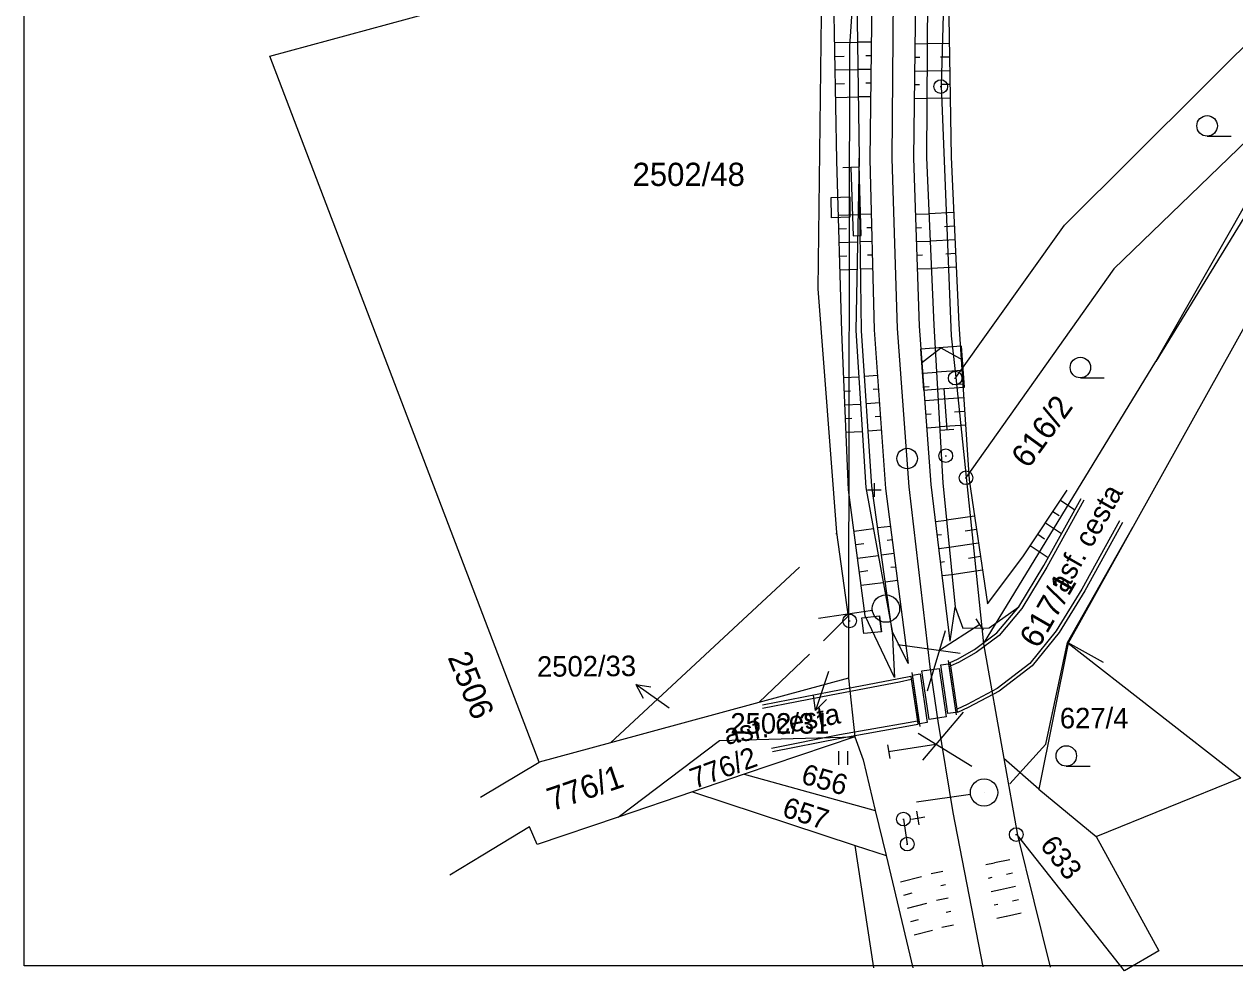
# Model space of a CAD drawing. Extents: x -558358 to -557517, y -1073786 to -1073189.
# Drawn here: x -558357.5 to -558268.9, y -1073784.4 to -1073715.2 of the extents above; entities that cross this region are included whole.
import ezdxf

# ---------------------------------------------------------------- set-up
doc = ezdxf.new("R2010")
doc.units = 0
for name, color, linetype in [('Body', 7, 'Continuous'), ('bubliny', 7, 'Continuous'), ('Hranice parcel', 7, 'Continuous'), ('Kolej', 7, 'Continuous'), ('Lomové body_krizky', 7, 'Continuous'), ('Návěst místo trati', 7, 'Continuous'), ('Návěst ostatní', 7, 'Continuous'), ('Parcelní čísla', 7, 'Continuous'), ('Plot - zábradlí', 7, 'Continuous'), ('Pop  PČ popisy', 7, 'Continuous'), ('Přejezd - štěrkové lože', 7, 'Continuous'), ('Sonda - šrafa - vrstevnice', 7, 'Continuous'), ('Svazek obcí údolí Desné', 7, 'Continuous'), ('Vedení nerozlišené', 7, 'Continuous'), ('Vrstva 1', 7, 'Continuous'), ('Značky kultur', 7, 'Continuous'), ('ŽKN drážní hranice', 7, 'Continuous')]:
    doc.layers.add(name, color=color, linetype=linetype)

msp = doc.modelspace()

# ---------------------------------------------------------------- linework, layer by layer
at = {"layer": 'Body'}
for p, q in [((-558298.48, -1073727.885), (-558297.122, -1073727.85)), ((-558297.117, -1073729.344), (-558298.447, -1073729.379)), ((-558296.242, -1073758.631), (-558294.944, -1073758.48)), ((-558294.789, -1073759.67), (-558296.101, -1073759.777))]:
    msp.add_line(p, q, dxfattribs=at)
for points in [[(-558297.122, -1073727.85), (-558297.117, -1073729.344), (-558298.447, -1073729.379), (-558298.48, -1073727.885), (-558297.122, -1073727.85)], [(-558298.447, -1073729.379), (-558298.447, -1073729.379), (-558298.48, -1073727.885), (-558298.48, -1073727.885)], [(-558297.117, -1073729.344), (-558297.117, -1073729.344), (-558297.122, -1073727.85), (-558297.122, -1073727.85)], [(-558294.944, -1073758.48), (-558294.789, -1073759.67), (-558296.101, -1073759.777), (-558296.242, -1073758.631), (-558294.944, -1073758.48)], [(-558294.789, -1073759.67), (-558294.789, -1073759.67), (-558294.944, -1073758.48), (-558294.944, -1073758.48)]]:
    msp.add_lwpolyline(points, dxfattribs=at)
at = {"layer": 'bubliny'}
for p, q in [((-558293.243, -1073773.359), (-558293.143, -1073773.359)), ((-558293.193, -1073773.359), (-558292.916, -1073775.189)), ((-558292.966, -1073775.189), (-558292.866, -1073775.189))]:
    msp.add_line(p, q, dxfattribs=at)
for points in [[(-558277.161, -1073751.663), (-558279.929, -1073756.667), (-558281.804, -1073759.714), (-558283.763, -1073762.159), (-558286.192, -1073764.005), (-558288.469, -1073765.207), (-558289.239, -1073765.561), (-558289.273, -1073765.325), (-558289.731, -1073762.148), (-558289.772, -1073761.903), (-558289.238, -1073761.663), (-558288.001, -1073760.952), (-558286.366, -1073759.742), (-558284.741, -1073757.826), (-558282.921, -1073754.818), (-558280.188, -1073749.911)], [(-558279.986, -1073750.021), (-558282.709, -1073754.924), (-558284.536, -1073757.951), (-558286.196, -1073759.921), (-558287.876, -1073761.169), (-558289.171, -1073761.901), (-558289.731, -1073762.148)], [(-558277.378, -1073751.548), (-558280.147, -1073756.544), (-558282.018, -1073759.595), (-558283.934, -1073761.983), (-558286.347, -1073763.816), (-558288.522, -1073764.981), (-558289.273, -1073765.325)], [(-558303.504, -1073765.012), (-558298.501, -1073764.02), (-558293.523, -1073763.084), (-558292.659, -1073762.9), (-558292.626, -1073763.133), (-558292.174, -1073766.197), (-558292.136, -1073766.428), (-558292.793, -1073766.551), (-558297.819, -1073767.452), (-558302.784, -1073768.441)], [(-558303.496, -1073765.249), (-558298.474, -1073764.266), (-558293.477, -1073763.32), (-558292.626, -1073763.133)], [(-558292.174, -1073766.197), (-558292.85, -1073766.309), (-558297.868, -1073767.199), (-558302.848, -1073768.199)]]:
    msp.add_lwpolyline(points, dxfattribs=at)
for centre in [(-558293.193, -1073773.359), (-558292.916, -1073775.189)]:
    msp.add_circle(centre, 0.5, dxfattribs=at)
at = {"layer": 'Hranice parcel'}
for p, q in [((-558339.57, -1073717.56), (-558299.09, -1073706.57)), ((-558319.85, -1073769.2), (-558339.57, -1073717.56)), ((-558274.72, -1073739.9), (-558262.39, -1073718.25)), ((-558259.48, -1073721.62), (-558281.15, -1073760.49)), ((-558287.34, -1073760.54), (-558274.72, -1073739.9)), ((-558300.796, -1073754.924), (-558314.63, -1073767.78)), ((-558281.15, -1073760.49), (-558283.28, -1073771.17)), ((-558281.15, -1073760.49), (-558268.5, -1073770.34)), ((-558300.06, -1073761.284), (-558303.78, -1073764.84)), ((-558297.22, -1073763.06), (-558303.78, -1073764.84)), ((-558303.78, -1073764.84), (-558314.63, -1073767.78)), ((-558296.74, -1073767.33), (-558304.84, -1073770.08)), ((-558314.63, -1073767.78), (-558319.85, -1073769.2)), ((-558283.28, -1073771.17), (-558285.85, -1073768.92)), ((-558324.15, -1073771.75), (-558319.85, -1073769.2)), ((-558304.84, -1073770.08), (-558308.63, -1073771.36)), ((-558304.84, -1073770.08), (-558295.26, -1073772.72)), ((-558279.1, -1073774.62), (-558268.5, -1073770.34)), ((-558308.63, -1073771.36), (-558314.07, -1073773.21)), ((-558308.63, -1073771.36), (-558296.72, -1073775.29)), ((-558283.28, -1073771.17), (-558279.1, -1073774.62)), ((-558314.07, -1073773.21), (-558319.99, -1073775.22)), ((-558323.98, -1073776), (-558326.38, -1073777.46))]:
    msp.add_line(p, q, dxfattribs=at)
for points in [[(-558289.37, -1073741.07), (-558281.4, -1073729.91), (-558261.12, -1073709.7)], [(-558260.45, -1073716.38), (-558262.32, -1073719.63), (-558274.72, -1073739.9)], [(-558262.39, -1073718.25), (-558277.79, -1073733.11), (-558288.61, -1073748.35)], [(-558314.07, -1073773.21), (-558306.66, -1073767.6), (-558296.74, -1073767.33)], [(-558319.99, -1073775.22), (-558320.55, -1073773.92), (-558323.98, -1073776)], [(-558279.1, -1073774.62), (-558274.51, -1073783), (-558277.02, -1073784.45), (-558284.85, -1073774.53)]]:
    msp.add_lwpolyline(points, dxfattribs=at)
at = {"layer": 'Kolej'}
msp.add_lwpolyline([(-558287.365, -1073784.156), (-558289.56, -1073772.871), (-558290.655, -1073766.206), (-558291.244, -1073762.209), (-558292.77, -1073749.061), (-558293.618, -1073737.469), (-558294.023, -1073725.055), (-558293.93, -1073713.176), (-558293.343, -1073701.022), (-558292.273, -1073689.007), (-558290.767, -1073677.306), (-558288.802, -1073665.65), (-558286.315, -1073653.735), (-558283.342, -1073641.942), (-558279.999, -1073630.567), (-558276.235, -1073619.431), (-558271.867, -1073608.038), (-558267.229, -1073597.243), (-558261.985, -1073586.238), (-558256.491, -1073575.8), (-558250.409, -1073565.278), (-558246.055, -1073558.303)], dxfattribs=at)
at = {"layer": 'Lomové body_krizky'}
for points in [[(-558288.463, -1073677.538), (-558289.796, -1073689.277), (-558290.88, -1073701.164), (-558291.444, -1073713.13), (-558291.51, -1073724.978), (-558290.98, -1073737.221), (-558290.303, -1073748.774), (-558289.412, -1073757.852), (-558288.852, -1073759.4), (-558286.909, -1073759.37), (-558284.741, -1073757.826)], [(-558288.463, -1073677.538), (-558287.551, -1073682.415), (-558288.544, -1073689.423), (-558289.374, -1073701.199), (-558289.889, -1073713.191), (-558289.693, -1073724.945), (-558289.132, -1073737.15), (-558288.385, -1073748.554), (-558287.031, -1073757.61), (-558284.468, -1073754.179), (-558281.215, -1073749.294)], [(-558293.853, -1073762.99), (-558295.99, -1073758.489), (-558297.205, -1073749.273), (-558297.706, -1073737.714), (-558298.061, -1073725.185), (-558298.29, -1073713.182), (-558297.21, -1073705.961)], [(-558297.21, -1073705.961), (-558296.594, -1073713.219), (-558296.433, -1073725.029), (-558296.684, -1073737.611), (-558295.948, -1073749.108), (-558294.01, -1073759.601), (-558293.853, -1073762.99)]]:
    msp.add_lwpolyline(points, dxfattribs=at)
at = {"layer": 'Návěst místo trati'}
for p, q in [((-558290.233, -1073741.874), (-558290.015, -1073744.866)), ((-558290.513, -1073744.903), (-558289.516, -1073744.83)), ((-558290.145, -1073746.779), (-558290.045, -1073746.779)), ((-558290.145, -1073746.779), (-558290.045, -1073746.779)), ((-558295.826, -1073749.287), (-558294.826, -1073749.287)), ((-558295.326, -1073748.787), (-558295.326, -1073749.787)), ((-558292.615, -1073773.362), (-558291.631, -1073773.184)), ((-558292.034, -1073773.765), (-558292.212, -1073772.781))]:
    msp.add_line(p, q, dxfattribs=at)
for points in [[(-558290.233, -1073741.874), (-558288.737, -1073741.765), (-558288.956, -1073738.773), (-558291.948, -1073738.992), (-558291.729, -1073741.984), (-558290.233, -1073741.874)], [(-558291.875, -1073739.991), (-558290.452, -1073738.882), (-558288.883, -1073739.772)]]:
    msp.add_lwpolyline(points, dxfattribs=at)
for centre, radius in [((-558292.922, -1073746.986), 0.75), ((-558290.095, -1073746.779), 0.5), ((-558290.095, -1073746.779), 0.5)]:
    msp.add_circle(centre, radius, dxfattribs=at)
at = {"layer": 'Návěst ostatní'}
for p, q in [((-558297.039, -1073725.696), (-558297.639, -1073725.715)), ((-558296.439, -1073725.676), (-558297.039, -1073725.696)), ((-558297.039, -1073725.696), (-558296.876, -1073730.693)), ((-558296.276, -1073730.674), (-558296.439, -1073725.676)), ((-558296.876, -1073730.693), (-558296.276, -1073730.674))]:
    msp.add_line(p, q, dxfattribs=at)
at = {"layer": 'Plot - zábradlí'}
for p, q in [((-558278.565, -1073761.91), (-558281.177, -1073760.435)), ((-558285.397, -1073770.771), (-558282.773, -1073767.881))]:
    msp.add_line(p, q, dxfattribs=at)
msp.add_lwpolyline([(-558282.773, -1073767.881), (-558281.177, -1073760.435), (-558276.416, -1073752.004)], dxfattribs=at)
at = {"layer": 'Pop  PČ popisy'}
for p, q in [((-558298.668, -1073762.558), (-558299.622, -1073765.403)), ((-558310.33, -1073765.253), (-558312.78, -1073763.52)), ((-558312.78, -1073763.52), (-558311.674, -1073763.69)), ((-558312.78, -1073763.52), (-558312.252, -1073764.507)), ((-558299.622, -1073765.403), (-558299.778, -1073764.295)), ((-558299.622, -1073765.403), (-558298.829, -1073764.613))]:
    msp.add_line(p, q, dxfattribs=at)
at = {"layer": 'Přejezd - štěrkové lože'}
for p, q in [((-558295.543, -1073716.537), (-558296.549, -1073716.525)), ((-558292.327, -1073716.638), (-558291.464, -1073716.648)), ((-558295.555, -1073717.537), (-558295.947, -1073717.532)), ((-558292.338, -1073717.638), (-558291.991, -1073717.642)), ((-558295.568, -1073718.536), (-558296.522, -1073718.525)), ((-558292.35, -1073718.638), (-558291.475, -1073718.647)), ((-558295.58, -1073719.536), (-558295.951, -1073719.532)), ((-558292.361, -1073719.637), (-558292.009, -1073719.641)), ((-558295.592, -1073720.536), (-558296.494, -1073720.525)), ((-558292.372, -1073720.637), (-558291.486, -1073720.647)), ((-558295.548, -1073729.117), (-558296.38, -1073729.138)), ((-558292.284, -1073729.113), (-558291.332, -1073729.081)), ((-558295.523, -1073730.117), (-558295.861, -1073730.125)), ((-558292.251, -1073730.114), (-558291.866, -1073730.101)), ((-558295.498, -1073731.116), (-558296.354, -1073731.138)), ((-558292.217, -1073731.112), (-558291.246, -1073731.08)), ((-558295.474, -1073732.116), (-558295.821, -1073732.125)), ((-558292.184, -1073732.113), (-558291.791, -1073732.099)), ((-558295.449, -1073733.116), (-558296.328, -1073733.138)), ((-558292.15, -1073733.112), (-558291.159, -1073733.078)), ((-558291.759, -1073740.745), (-558290.778, -1073740.674)), ((-558295.098, -1073740.923), (-558296.043, -1073740.991)), ((-558295.027, -1073741.92), (-558295.406, -1073741.948)), ((-558291.687, -1073741.742), (-558291.3, -1073741.714)), ((-558294.956, -1073742.918), (-558295.906, -1073742.986)), ((-558291.615, -1073742.74), (-558290.661, -1073742.671)), ((-558294.884, -1073743.915), (-558295.266, -1073743.942)), ((-558291.542, -1073743.738), (-558291.166, -1073743.71)), ((-558294.813, -1073744.913), (-558295.77, -1073744.981)), ((-558291.47, -1073744.735), (-558290.544, -1073744.667)), ((-558294.15, -1073751.946), (-558295.067, -1073752.065)), ((-558290.838, -1073751.581), (-558290.037, -1073751.483)), ((-558294.022, -1073752.938), (-558294.384, -1073752.984)), ((-558290.717, -1073752.574), (-558290.406, -1073752.536)), ((-558293.893, -1073753.929), (-558294.789, -1073754.045)), ((-558290.595, -1073753.567), (-558289.842, -1073753.474)), ((-558293.765, -1073754.921), (-558294.119, -1073754.967)), ((-558290.473, -1073754.559), (-558290.182, -1073754.524)), ((-558290.352, -1073755.552), (-558289.646, -1073755.466)), ((-558293.637, -1073755.913), (-558294.511, -1073756.026)), ((-558289.764, -1073760.35), (-558289.412, -1073757.852)), ((-558287.609, -1073759.129), (-558290.55, -1073761.026)), ((-558287.338, -1073759.549), (-558287.88, -1073758.709)), ((-558291.441, -1073763.981), (-558290.126, -1073759.563)), ((-558289.042, -1073761.243), (-558293.609, -1073760.619)), ((-558289.319, -1073765.724), (-558289.899, -1073761.77)), ((-558292.589, -1073762.629), (-558292.006, -1073766.588)), ((-558288.812, -1073765.538), (-558291.802, -1073769.047)), ((-558292.114, -1073767.071), (-558288.189, -1073769.489)), ((-558294.357, -1073767.931), (-558294.201, -1073768.919)), ((-558294.279, -1073768.425), (-558290.822, -1073767.88)), ((-558287.161, -1073776.688), (-558286.528, -1073776.56)), ((-558290.3, -1073777.183), (-558291.169, -1073777.352)), ((-558286.963, -1073777.668), (-558286.703, -1073777.615)), ((-558290.109, -1073778.164), (-558290.454, -1073778.231)), ((-558286.765, -1073778.648), (-558286.096, -1073778.513)), ((-558289.917, -1073779.145), (-558290.775, -1073779.313)), ((-558286.567, -1073779.629), (-558286.292, -1073779.573)), ((-558289.726, -1073780.127), (-558290.067, -1073780.193)), ((-558286.369, -1073780.609), (-558285.665, -1073780.466)), ((-558289.535, -1073781.109), (-558290.381, -1073781.274))]:
    msp.add_line(p, q, dxfattribs=at)
for points in [[(-558236.565, -1073541.181), (-558242.627, -1073550.035), (-558251.802, -1073564.356), (-558258.077, -1073574.962), (-558263.679, -1073585.424), (-558268.893, -1073596.634), (-558273.555, -1073607.365), (-558277.841, -1073618.92), (-558281.554, -1073630.049), (-558284.863, -1073641.542), (-558287.933, -1073653.35), (-558290.359, -1073665.391), (-558292.442, -1073677.056), (-558293.843, -1073688.831), (-558294.976, -1073700.921), (-558295.502, -1073713.202), (-558295.648, -1073725.09), (-558295.338, -1073737.572), (-558294.508, -1073749.176), (-558292.854, -1073761.969)], [(-558289.764, -1073760.35), (-558291.17, -1073748.874), (-558292.009, -1073737.3), (-558292.422, -1073725.025), (-558292.288, -1073713.18), (-558291.762, -1073701.106), (-558290.619, -1073689.204), (-558289.112, -1073677.435), (-558287.165, -1073665.923), (-558284.764, -1073654.08), (-558281.791, -1073642.378), (-558278.307, -1073631.081), (-558274.714, -1073619.924), (-558270.318, -1073608.64), (-558265.699, -1073597.902), (-558260.505, -1073586.941), (-558255.049, -1073576.609), (-558248.928, -1073566.176), (-558239.895, -1073551.788), (-558235.828, -1073545.738)], [(-558292.854, -1073761.969), (-558294.01, -1073759.601), (-558295.495, -1073749.015), (-558296.27, -1073737.659), (-558296.433, -1073725.029)]]:
    msp.add_lwpolyline(points, dxfattribs=at)
for points in [[(-558290.457, -1073762.083), (-558289.885, -1073762.005), (-558289.362, -1073765.55), (-558289.936, -1073765.638)], [(-558292.54, -1073762.834), (-558291.975, -1073762.745), (-558291.449, -1073766.301), (-558292.019, -1073766.38)], [(-558291.836, -1073762.516), (-558290.589, -1073762.332), (-558290.071, -1073765.874), (-558291.31, -1073766.072)]]:
    msp.add_lwpolyline(points, close=True, dxfattribs=at)
at = {"layer": 'Sonda - šrafa - vrstevnice'}
for p, q in [((-558298.225, -1073716.572), (-558296.549, -1073716.54)), ((-558289.832, -1073716.622), (-558291.464, -1073716.649)), ((-558298.206, -1073717.572), (-558297.538, -1073717.559)), ((-558289.815, -1073717.622), (-558290.477, -1073717.633)), ((-558298.187, -1073718.571), (-558296.521, -1073718.539)), ((-558289.798, -1073718.622), (-558291.475, -1073718.649)), ((-558298.168, -1073719.571), (-558297.504, -1073719.558)), ((-558289.782, -1073719.621), (-558290.461, -1073719.632)), ((-558298.149, -1073720.571), (-558296.494, -1073720.539)), ((-558289.765, -1073720.621), (-558291.486, -1073720.65)), ((-558297.948, -1073729.186), (-558296.515, -1073729.145)), ((-558289.506, -1073729.003), (-558291.332, -1073729.087)), ((-558289.461, -1073730.003), (-558290.192, -1073730.036)), ((-558297.919, -1073730.185), (-558297.366, -1073730.169)), ((-558289.415, -1073731.001), (-558291.246, -1073731.085)), ((-558297.891, -1073731.185), (-558296.555, -1073731.147)), ((-558297.863, -1073732.184), (-558297.348, -1073732.169)), ((-558289.369, -1073732), (-558290.102, -1073732.034)), ((-558297.834, -1073733.184), (-558296.595, -1073733.149)), ((-558289.323, -1073732.999), (-558291.159, -1073733.083)), ((-558288.91, -1073740.544), (-558290.778, -1073740.666)), ((-558297.561, -1073741.058), (-558296.466, -1073741.011)), ((-558288.844, -1073741.541), (-558289.594, -1073741.591)), ((-558297.518, -1073742.057), (-558297.072, -1073742.038)), ((-558297.474, -1073743.056), (-558296.339, -1073743.007)), ((-558288.779, -1073742.539), (-558290.661, -1073742.662)), ((-558297.431, -1073744.055), (-558296.969, -1073744.035)), ((-558288.714, -1073743.537), (-558289.469, -1073743.587)), ((-558297.388, -1073745.054), (-558296.211, -1073745.003)), ((-558288.648, -1073744.535), (-558290.544, -1073744.659)), ((-558281.701, -1073750.023), (-558280.643, -1073750.728)), ((-558287.99, -1073751.193), (-558290.036, -1073751.499)), ((-558282.255, -1073750.855), (-558281.805, -1073751.155)), ((-558296.807, -1073752.292), (-558295.394, -1073752.106)), ((-558287.842, -1073752.182), (-558288.681, -1073752.308)), ((-558282.809, -1073751.688), (-558281.619, -1073752.48)), ((-558283.364, -1073752.52), (-558282.861, -1073752.855)), ((-558296.676, -1073753.284), (-558296.091, -1073753.207)), ((-558287.695, -1073753.172), (-558289.84, -1073753.492)), ((-558283.918, -1073753.352), (-558282.595, -1073754.233)), ((-558296.546, -1073754.275), (-558295.031, -1073754.075)), ((-558287.547, -1073754.161), (-558288.425, -1073754.292)), ((-558296.415, -1073755.266), (-558295.788, -1073755.183)), ((-558287.399, -1073755.149), (-558289.644, -1073755.485)), ((-558296.284, -1073756.258), (-558294.667, -1073756.045)), ((-558285.419, -1073776.326), (-558286.526, -1073776.567)), ((-558293.404, -1073777.941), (-558291.883, -1073777.549)), ((-558285.207, -1073777.303), (-558285.648, -1073777.399)), ((-558293.154, -1073778.91), (-558292.564, -1073778.757)), ((-558284.994, -1073778.28), (-558286.095, -1073778.52)), ((-558292.904, -1073779.878), (-558291.476, -1073779.51)), ((-558284.781, -1073779.258), (-558285.22, -1073779.353)), ((-558284.568, -1073780.234), (-558285.664, -1073780.473)), ((-558292.654, -1073780.847), (-558292.102, -1073780.704)), ((-558292.404, -1073781.815), (-558291.07, -1073781.47))]:
    msp.add_line(p, q, dxfattribs=at)
at = {"layer": 'Svazek obcí údolí Desné'}
for p, q in [((-558289.37, -1073741.07), (-558288.61, -1073748.35)), ((-558288.61, -1073748.35), (-558287.34, -1073760.54)), ((-558297.21, -1073758.56), (-558298.08, -1073752.4)), ((-558297.21, -1073758.56), (-558297.22, -1073763.06)), ((-558287.34, -1073760.54), (-558285.85, -1073768.92)), ((-558297.22, -1073763.06), (-558296.74, -1073767.33)), ((-558285.85, -1073768.92), (-558284.85, -1073774.53)), ((-558295.26, -1073772.72), (-558294.47, -1073776.03)), ((-558296.72, -1073775.29), (-558294.47, -1073776.03)), ((-558284.85, -1073774.53), (-558282.455, -1073784.177))]:
    msp.add_line(p, q, dxfattribs=at)
for points in [[(-558237.23, -1073540.41), (-558250.35, -1073559.71), (-558264.4, -1073584.99), (-558277.08, -1073613.49), (-558283.33, -1073632.3), (-558290.3, -1073658.29), (-558296.01, -1073700.28), (-558297.13, -1073716.84), (-558297.21, -1073758.56)], [(-558287.25, -1073676.53), (-558288.33, -1073687.34), (-558288.98, -1073695.83), (-558290.03, -1073705.01), (-558290.44, -1073719.74), (-558289.69, -1073738.01), (-558289.37, -1073741.07)], [(-558298.08, -1073752.4), (-558299.44, -1073734.57), (-558299.09, -1073706.57)], [(-558296.74, -1073767.33), (-558296.14, -1073769.02), (-558295.26, -1073772.72)], [(-558295.354, -1073784.245), (-558296.72, -1073775.29)], [(-558294.47, -1073776.03), (-558292.513, -1073784.226)]]:
    msp.add_lwpolyline(points, dxfattribs=at)
at = {"layer": 'Vedení nerozlišené'}
for p, q in [((-558295.463, -1073758.109), (-558299.422, -1073758.682)), ((-558294.473, -1073757.966), (-558294.473, -1073757.966)), ((-558288.288, -1073771.552), (-558292.247, -1073772.125)), ((-558287.298, -1073771.409), (-558287.298, -1073771.409))]:
    msp.add_line(p, q, dxfattribs=at)
for centre in [(-558294.473, -1073757.966), (-558287.298, -1073771.409)]:
    msp.add_circle(centre, 1, dxfattribs=at)
at = {"layer": 'Vrstva 1'}
for p, q in [((-558357.534, -1073784.088), (-558357.534, -1073190.088)), ((-558298.145, -1073752.46), (-558298.072, -1073752.46)), ((-558299.043, -1073760.312), (-558297.22, -1073758.489)), ((-557516.534, -1073784.088), (-558357.534, -1073784.088))]:
    msp.add_line(p, q, dxfattribs=at)
at = {"layer": 'Značky kultur'}
for p, q in [((-558270.973, -1073723.41), (-558269.223, -1073723.41)), ((-558280.246, -1073741.084), (-558278.496, -1073741.084)), ((-558297.932, -1073769.39), (-558297.932, -1073768.385)), ((-558297.262, -1073769.39), (-558297.262, -1073768.385)), ((-558281.278, -1073769.487), (-558279.528, -1073769.487))]:
    msp.add_line(p, q, dxfattribs=at)
for centre in [(-558270.973, -1073722.66), (-558280.246, -1073740.334), (-558281.278, -1073768.737)]:
    msp.add_circle(centre, 0.75, dxfattribs=at)
at = {"layer": 'ŽKN drážní hranice'}
for p, q in [((-558290.515, -1073719.78), (-558290.415, -1073719.78)), ((-558289.458, -1073741.103), (-558289.358, -1073741.103)), ((-558288.668, -1073748.39), (-558288.568, -1073748.39)), ((-558297.182, -1073758.862), (-558297.082, -1073758.862)), ((-558284.994, -1073774.485), (-558284.894, -1073774.485))]:
    msp.add_line(p, q, dxfattribs=at)
for centre in [(-558290.465, -1073719.78), (-558289.408, -1073741.103), (-558288.618, -1073748.39), (-558297.132, -1073758.862), (-558284.944, -1073774.485)]:
    msp.add_circle(centre, 0.499, dxfattribs=at)

# ---------------------------------------------------------------- texts
at = {"layer": 'bubliny'}
for rotation, p in [(60.40672, (-558281.324, -1073756.904)), (10.70475, (-558306.162, -1073767.928))]:
    msp.add_text('asf. cesta', height=1.5, rotation=rotation, dxfattribs=at).set_placement(p)
at = {"layer": 'Parcelní čísla'}
for s, height, p in [('2502/48', 1.7, (-558313.014, -1073727.054)), ('2502/31', 1.5, (-558305.857, -1073767.106)), ('627/4', 1.5, (-558281.748, -1073766.72))]:
    msp.add_text(s, height=height, dxfattribs=at).set_placement(p)
for s, height, rotation, p in [('616/2', 1.7, 54, (-558284.059, -1073747.791)), ('617/1', 1.7, 60, (-558283.329, -1073760.958)), ('2506', 1.7, 292, (-558326.567, -1073761.522)), ('2502/33', 1.5, 0.44646, (-558320.005, -1073762.951)), ('776/2', 1.5, 20, (-558308.48, -1073771.154)), ('776/1', 1.7, 18.8548, (-558318.911, -1073772.792)), ('656', 1.5, 344, (-558300.763, -1073770.723)), ('657', 1.5, 342, (-558302.151, -1073773.131)), ('633', 1.5, 308, (-558283.264, -1073775.294))]:
    msp.add_text(s, height=height, rotation=rotation, dxfattribs=at).set_placement(p)

doc.saveas('drawing.dxf')
